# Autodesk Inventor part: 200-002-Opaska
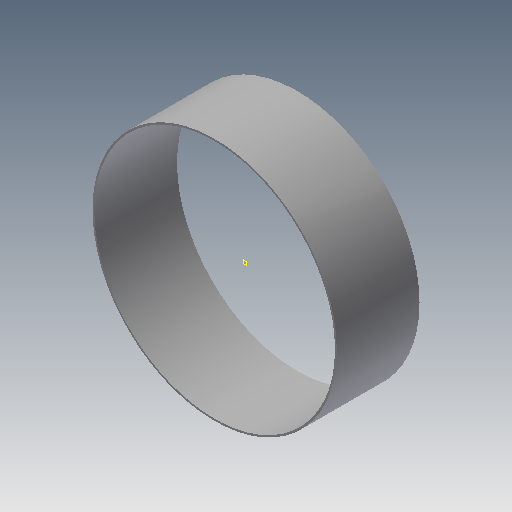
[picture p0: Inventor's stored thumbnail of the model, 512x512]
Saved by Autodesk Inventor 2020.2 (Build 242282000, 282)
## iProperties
Created: 2014-03
Part Number: 200-002-Opaska
Material: Stal
Document SubType Name: Modeling
Designer: F.Stasiak
Density: 7.85 g/cm^3
Appearance: Stal
Catalog Web Link: www.expertbooks.pl
Manager: www.cadconsulting.pl
Company: Fabian Stasiak CAD Consulting
Author: F.Stasiak
Subject: Zbiór ćwiczeń. Autodesk Inventor 2020. Kurs Professional
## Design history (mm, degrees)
node "Płaszczyzna konstrukcyjna2"
sketch "Szkic1"
  geometry: C1 r 800 at (0, 0) reference; C2 r 812 at (0, 0); 1 further point
  constraints: 1 centre point
  dimensions: "d0" = 12 radial gap between concentric circles of C2 C1; "d5" = 1600 diameter of C1 (derived)
extrude "Wyciągnięcie proste1" new body sketch "Szkic1" distance "d1" = 200; taper "d3" = 0 deg; dims "d2" = 350, "d4" = 0
node "Bryła1"
